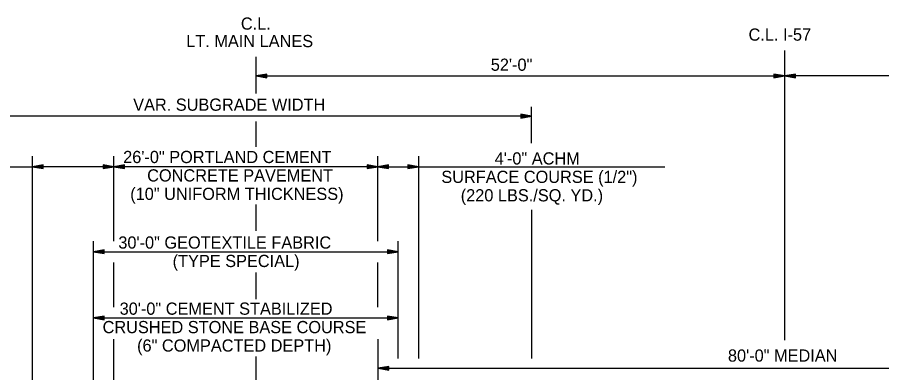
# Model space of a CAD drawing. Extents: x 1734743 to 1735935, y 759845 to 763831.
# Drawn here: x 1735668.6 to 1735753.6, y 760333.4 to 760368.3 of the extents above; entities that cross this region are included whole.
import ezdxf

# ---------------------------------------------------------------- set-up
doc = ezdxf.new("R2010")
doc.units = 0
for name, color, linetype in [('10', 7, 'Continuous'), ('19', 7, 'Continuous'), ('7', 7, 'Continuous'), ('9', 7, 'Continuous')]:
    doc.layers.add(name, color=color, linetype=linetype)

msp = doc.modelspace()

# ---------------------------------------------------------------- linework, layer by layer
at = {"layer": '19'}
for p, q in [((1735693.126, 760362.749), (1735692.076, 760362.565)), ((1735692.076, 760362.565), (1735693.126, 760362.381)), ((1735693.126, 760362.652), (1735692.356, 760362.591)), ((1735692.356, 760362.539), (1735693.126, 760362.469)), ((1735693.126, 760362.381), (1735693.126, 760362.749)), ((1735743.028, 760362.749), (1735743.028, 760362.381)), ((1735744.078, 760362.565), (1735743.028, 760362.749)), ((1735743.798, 760362.591), (1735743.028, 760362.652)), ((1735743.028, 760362.381), (1735744.078, 760362.565)), ((1735743.028, 760362.469), (1735743.798, 760362.539)), ((1735745.128, 760362.749), (1735744.078, 760362.565)), ((1735744.078, 760362.565), (1735745.128, 760362.381)), ((1735745.128, 760362.652), (1735744.358, 760362.591)), ((1735744.358, 760362.539), (1735745.128, 760362.469)), ((1735745.128, 760362.381), (1735745.128, 760362.749)), ((1735719.172, 760355.965), (1735719.172, 760359.522)), ((1735719.172, 760358.613), (1735658.801, 760358.613)), ((1735718.122, 760358.797), (1735718.122, 760358.429)), ((1735719.172, 760358.613), (1735718.122, 760358.797)), ((1735718.892, 760358.639), (1735718.122, 760358.7)), ((1735718.122, 760358.429), (1735719.172, 760358.613)), ((1735718.122, 760358.517), (1735718.892, 760358.587)), ((1735670.076, 760323.05), (1735670.076, 760354.675)), ((1735678.076, 760346.317), (1735678.076, 760354.675)), ((1735704.071, 760346.317), (1735704.071, 760354.675)), ((1735708.074, 760354.675), (1735708.074, 760334.778)), ((1735634.219, 760353.63), (1735670.076, 760353.63)), ((1735671.126, 760353.817), (1735670.076, 760353.634)), ((1735678.076, 760353.634), (1735670.076, 760353.634)), ((1735670.076, 760353.634), (1735671.126, 760353.45)), ((1735671.126, 760353.721), (1735670.356, 760353.66)), ((1735670.356, 760353.608), (1735671.126, 760353.537)), ((1735671.126, 760353.45), (1735671.126, 760353.817)), ((1735677.026, 760353.818), (1735677.026, 760353.45)), ((1735678.076, 760353.634), (1735677.026, 760353.818)), ((1735677.796, 760353.66), (1735677.026, 760353.721)), ((1735677.026, 760353.45), (1735678.076, 760353.634)), ((1735677.026, 760353.538), (1735677.796, 760353.608)), ((1735679.126, 760353.817), (1735678.076, 760353.634)), ((1735704.076, 760353.634), (1735678.076, 760353.634)), ((1735678.076, 760353.634), (1735679.126, 760353.45)), ((1735679.126, 760353.721), (1735678.356, 760353.66)), ((1735678.356, 760353.608), (1735679.126, 760353.537)), ((1735679.126, 760353.45), (1735679.126, 760353.817)), ((1735703.021, 760353.818), (1735703.021, 760353.45)), ((1735704.071, 760353.634), (1735703.021, 760353.818)), ((1735703.791, 760353.66), (1735703.021, 760353.721)), ((1735703.021, 760353.45), (1735704.071, 760353.634)), ((1735703.021, 760353.538), (1735703.791, 760353.608)), ((1735705.121, 760353.817), (1735704.071, 760353.634)), ((1735704.071, 760353.634), (1735708.074, 760353.634)), ((1735704.071, 760353.634), (1735705.121, 760353.45)), ((1735705.121, 760353.721), (1735704.351, 760353.66)), ((1735704.351, 760353.608), (1735705.121, 760353.537)), ((1735705.121, 760353.45), (1735705.121, 760353.817)), ((1735707.024, 760353.818), (1735707.024, 760353.45)), ((1735708.074, 760353.634), (1735707.024, 760353.818)), ((1735707.794, 760353.66), (1735707.024, 760353.721)), ((1735707.024, 760353.45), (1735708.074, 760353.634)), ((1735707.024, 760353.538), (1735707.794, 760353.608)), ((1735708.074, 760353.634), (1735732.284, 760353.634)), ((1735719.172, 760349.411), (1735719.172, 760334.778)), ((1735676.077, 760325.139), (1735676.077, 760346.321)), ((1735706.071, 760334.778), (1735706.071, 760346.317)), ((1735677.127, 760345.458), (1735676.077, 760345.275)), ((1735677.127, 760345.362), (1735676.357, 760345.301)), ((1735677.127, 760345.091), (1735677.127, 760345.458)), ((1735705.021, 760345.458), (1735705.021, 760345.091)), ((1735706.071, 760345.275), (1735705.021, 760345.458)), ((1735705.791, 760345.301), (1735705.021, 760345.362)), ((1735676.077, 760345.275), (1735706.071, 760345.275)), ((1735676.077, 760345.275), (1735677.127, 760345.091)), ((1735676.357, 760345.248), (1735677.127, 760345.178)), ((1735705.021, 760345.091), (1735706.071, 760345.275)), ((1735705.021, 760345.178), (1735705.791, 760345.248)), ((1735678.076, 760339.815), (1735678.076, 760344.225)), ((1735704.071, 760339.815), (1735704.071, 760344.225)), ((1735677.127, 760338.956), (1735676.077, 760338.773)), ((1735676.077, 760338.773), (1735706.071, 760338.773)), ((1735676.077, 760338.773), (1735677.127, 760338.589)), ((1735677.127, 760338.86), (1735676.357, 760338.799)), ((1735676.357, 760338.746), (1735677.127, 760338.676)), ((1735677.127, 760338.589), (1735677.127, 760338.956)), ((1735705.021, 760338.956), (1735705.021, 760338.589)), ((1735706.071, 760338.773), (1735705.021, 760338.956)), ((1735705.791, 760338.799), (1735705.021, 760338.86)), ((1735705.021, 760338.589), (1735706.071, 760338.773)), ((1735705.021, 760338.676), (1735705.791, 760338.746)), ((1735678.082, 760325.267), (1735678.082, 760336.69)), ((1735704.076, 760334.485), (1735704.076, 760336.69)), ((1735704.076, 760326.452), (1735704.076, 760334.485)), ((1735705.126, 760334.009), (1735704.076, 760333.825)), ((1735704.076, 760333.825), (1735784.076, 760333.825)), ((1735704.076, 760333.825), (1735705.126, 760333.642)), ((1735705.126, 760333.913), (1735704.356, 760333.852)), ((1735704.356, 760333.799), (1735705.126, 760333.729)), ((1735705.126, 760333.642), (1735705.126, 760334.009))]:
    msp.add_line(p, q, dxfattribs=at)
at = {"layer": '7'}
for p, q in [((1735744.078, 760336.593), (1735744.078, 760365.084)), ((1735692.076, 760360.825), (1735692.076, 760364.439)), ((1735692.076, 760355.584), (1735692.076, 760358.083)), ((1735692.076, 760347.334), (1735692.076, 760349.929)), ((1735692.076, 760340.609), (1735692.076, 760343.252)), ((1735692.076, 760318.862), (1735692.076, 760334.993))]:
    msp.add_line(p, q, dxfattribs=at)
at = {"layer": '9'}
for p in [(1735692.076, 760362.565), (1735796.076, 760362.565)]:
    msp.add_line(p, (1735744.078, 760362.565), dxfattribs=at)

# ---------------------------------------------------------------- texts
at = {"layer": '10'}
msp.add_text('52\'-0"', height=1.2, dxfattribs=at).set_placement((1735715.169, 760363.071))
at = {"layer": '19'}
for s, p in [('C.L.', (1735690.585, 760367.115)), ('LT. MAIN LANES', (1735685.209, 760365.399)), ('C.L. I-57', (1735740.525, 760366.032)), ('VAR. SUBGRADE WIDTH', (1735679.99, 760359.143)), ('26\'-0" PORTLAND CEMENT', (1735679.005, 760353.998)), ('4\'-0" ACHM ', (1735715.558, 760353.856)), ('CONCRETE PAVEMENT', (1735681.367, 760352.186)), ('SURFACE COURSE (1/2")', (1735710.304, 760352.043)), ('(10" UNIFORM THICKNESS)', (1735679.7, 760350.373)), ('(220 LBS./SQ. YD.)', (1735712.213, 760350.231)), ('30\'-0" GEOTEXTILE FABRIC', (1735678.53, 760345.586)), ('(TYPE SPECIAL)', (1735683.873, 760343.773)), ('30\'-0" CEMENT STABILIZED ', (1735678.66, 760339.084)), ('CRUSHED STONE BASE COURSE', (1735676.982, 760337.271)), ('(6" COMPACTED DEPTH)', (1735680.375, 760335.459)), ('80\'-0" MEDIAN', (1735738.498, 760334.472))]:
    msp.add_text(s, height=1.2, dxfattribs=at).set_placement(p)

doc.saveas('drawing.dxf')
